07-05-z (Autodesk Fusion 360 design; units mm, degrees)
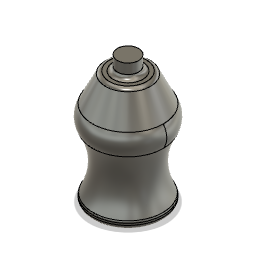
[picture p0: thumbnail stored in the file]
sketch "スケッチ1" plane through (0, 0, 0) normal (0, 1, 0) x axis (1, 0, 0)
  circle C1 centre (0, 0) radius 25
  point P1 (0, 0)
  point P2 (0, 0)
  coincident P1 P2
  dimension "d1" diameter C1 = 50
extrude "押し出し1" new body sketch "スケッチ1" along normal blind 5
work_plane "作業平面1" AlongDistance 20
sketch "スケッチ2" plane through (0, 25, 0) normal (0, 1, 0) x axis (1, 0, 0)
  circle C1 centre (0, 0) radius 20
  point P1 (0, 0)
  point P2 (0, 0)
  coincident P1 P2
  dimension "d5" diameter C1 = 40
work_plane "作業平面2" AlongDistance 20
sketch "スケッチ3" plane through (0, 45, 0) normal (0, 1, 0) x axis (1, 0, 0)
  circle C1 centre (0, 0) radius 25
loft "ロフト1" sketch "スケッチ2" + "スケッチ3"
work_plane "作業平面3" AlongDistance 15
sketch "スケッチ4" plane through (0, 60, 0) normal (0, 1, 0) x axis (1, 0, 0)
  circle C1 centre (0, 0) radius 25
sketch "スケッチ5" plane through (0, 0, 0) normal (0, 0, 1) x axis (1, 0, 0)
  line L1 (-25, 60) -> (25, 60)
  line L2 (25, 45) -> (-25, 45)
  arc A1 centre (-14.3816, 52.5) radius 13 clockwise from (-25, 45) to (-25, 60)
  arc A2 centre (14.3816, 52.5) radius 13 clockwise from (25, 60) to (25, 45)
  point P2 (-25, 60)
  point P9 (-25, 60)
  point P3 (-25, 45)
  point P10 (-25, 45)
  point P5 (25, 60)
  point P8 (25, 60)
  point P6 (25, 45)
  point P11 (25, 45)
  coincident P2 P9
  coincident P3 P10
  coincident P5 P8
  coincident P6 P11
  equal A1 A2
  dimension "d8" radius A1 = 13
sketch "スケッチ6" plane through (0, 0, 0) normal (1, 0, 0) x axis (0, 0, -1)
  line L1 (-25, 60) -> (25, 60)
  line L2 (25, 45) -> (-25, 45)
  arc A1 centre (-14.3816, 52.5) radius 13 clockwise from (-25, 45) to (-25, 60)
  arc A2 centre (14.3816, 52.5) radius 13 clockwise from (25, 60) to (25, 45)
  point P2 (-25, 60)
  point P9 (-25, 60)
  point P3 (-25, 45)
  point P10 (-25, 45)
  point P6 (25, 45)
  point P11 (25, 45)
  point P5 (25, 60)
  point P8 (25, 60)
  coincident P2 P9
  coincident P3 P10
  coincident P6 P11
  coincident P5 P8
  equal A1 A2
  dimension "d9" radius A1 = 13
loft "ロフト2" sketch "スケッチ4"
work_plane "作業平面4" AlongDistance 20
sketch "スケッチ7" plane through (0, 80, 0) normal (0, 1, 0) x axis (1, 0, 0)
  circle C1 centre (0, 0) radius 15
  point P1 (0, 0)
  point P2 (0, 0)
  coincident P1 P2
  dimension "d12" diameter C1 = 30
loft "ロフト3" sketch "スケッチ7"
sketch "スケッチ8" plane through (0, 80, 0) normal (0, 1, 0) x axis (-1, 0, 0)
  circle C1 centre (0, 0) radius 15
  circle C2 centre (0, 0) radius 7.5
  point P1 (0, 0)
  point P3 (0, 0)
  coincident P1 P3
  dimension "d13" diameter C2 = 15
extrude "押し出し2" add sketch "スケッチ8" profile of C2 along normal blind 10
fillet "フィレット" radius 3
